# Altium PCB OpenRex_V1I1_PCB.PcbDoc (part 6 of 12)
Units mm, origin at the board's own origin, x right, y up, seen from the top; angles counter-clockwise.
Board outline 70 x 95 mm, 10 copper layers (L1, L2, L3, L4 (PWR), L5 (PWR), L6 (PWR), L7 (PWR), L8, L9, L10), stack 1.632 mm thick; 1080 components, 708 nets, 3831 pads, 2373 vias.
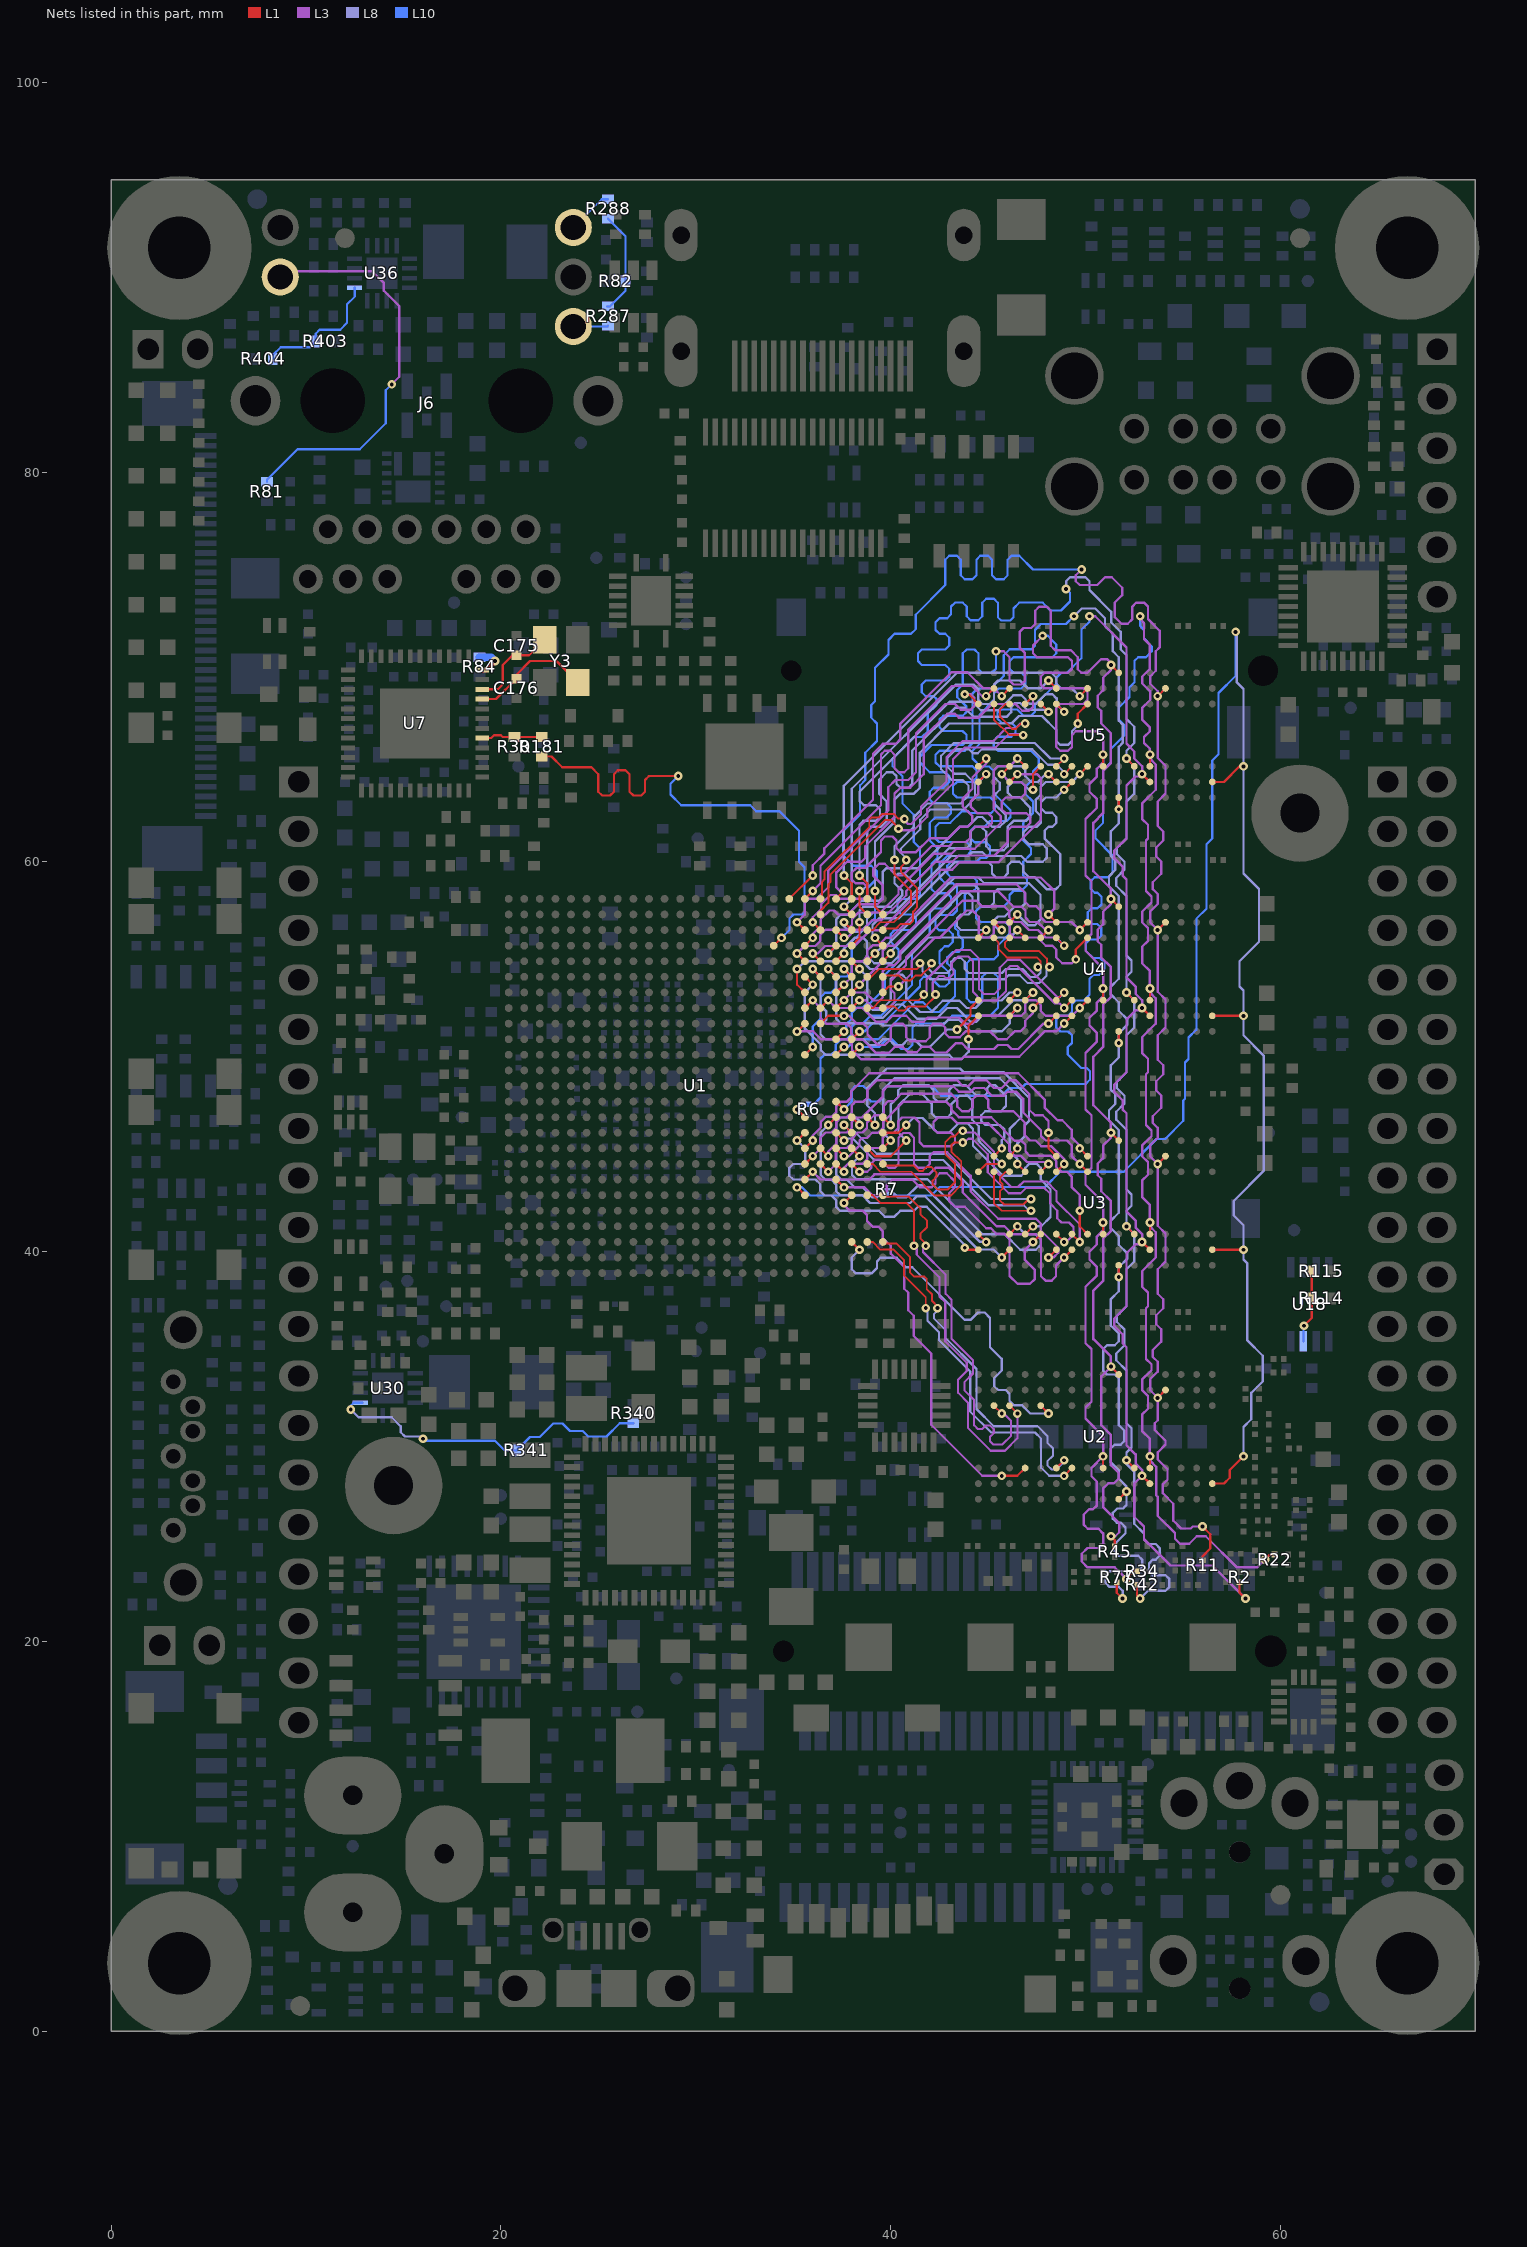
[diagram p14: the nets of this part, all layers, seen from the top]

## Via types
v1: diameter 0.45, hole 0.2, L1 to L10, tented both sides, 2369 vias
v2: diameter 1, hole 0.5, L1 to L10, tented top, 4 vias

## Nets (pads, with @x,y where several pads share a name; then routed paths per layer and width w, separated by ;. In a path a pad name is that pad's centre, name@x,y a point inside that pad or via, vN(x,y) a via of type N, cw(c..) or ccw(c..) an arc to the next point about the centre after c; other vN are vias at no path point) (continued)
DRAM_D16: U1.AB7 U3.E3 | length 19.1
  L1 w0.114: U1.AB7@37.2,43.7 v1(37.6,43.3) ; v1(47.3,40.5) U3.E3@47.7,40.9
  L3 w0.12: v1(37.6,43.3) 38.656,43.3 39.056,42.9 39.6,42.9 39.793,43.093 39.793,43.393 40.085,43.685 41.115,43.685 41.5,43.3 42.1,43.3 42.3,43.5 42.3,43.8 42.52,44.02 42.88,44.02 43.3,43.6 43.3,43.3 43,43 43,42.6 43.3,42.3 43.8,42.3 44.9,41.2 45.14,41.2 45.418,40.922 45.822,40.922 46.1,40.644 46.1,38.756 46.506,38.35 47.15,38.35 47.4,38.6 47.4,39.055 46.885,39.571 46.885,40.085 v1(47.3,40.5)
DRAM_D17: U1.AA8 U3.F7 | length 19.1
  L1 w0.114: U1.AA8@36.4,44.5 v1(36.8,44.1) ; U3.F7@48.5,44.1 v1(48.9,44.5)
  L3 w0.12: v1(36.8,44.1) 37.185,44.485 37.185,45.085 37.415,45.315 37.759,45.315 38.009,45.565 38.009,45.809 38.315,46.115 38.559,46.115 38.785,46.341 38.785,46.629 39.156,47 39.5,47 39.656,47.156 39.656,47.5 39.871,47.715 40.159,47.715 40.544,48.1 43.1,48.1 43.415,47.785 43.415,47.441 43.656,47.2 44,47.2 44.215,47.415 44.215,47.815 44.385,47.985 44.815,47.985 45,47.8 45,47.4 45.2,47.2 46.3,47.2 46.885,46.615 46.885,45.971 47.155,45.7 47.444,45.7 47.685,45.459 47.744,45.4 48.255,45.4 48.9,44.755 v1(48.9,44.5)
DRAM_D18: U1.AB9 U3.H3 | length 19.1
  L1 w0.114: U1.AB9@37.2,45.3 v1(37.6,44.9) ; v1(49.7,42.1) 49.7,41.3 U3.H3@50.1,40.9
  L3 w0.12: v1(37.6,44.9) 37.856,44.9 38.4,45.444 38.4,45.7 38.535,45.835 38.791,45.835 39.056,46.1 39.344,46.1 39.615,46.371 39.615,46.659 40.656,47.7 42.844,47.7 43.1,47.444 43.1,47.3 43.5,46.9 45.155,46.9 46.371,45.685 46.715,45.685 46.915,45.485 46.915,45.141 47.141,44.915 48.229,44.915 48.5,44.644 48.5,44.356 48.771,44.085 49.059,44.085 49.285,43.859 49.285,43.315 49.7,42.9 v1(49.7,42.1)
DRAM_D19: U1.Y9 U3.H8 | length 19.1
  L1 w0.114: U1.Y9@35.6,45.3 v1(36,45.7) ; v1(49.7,45.3) U3.H8@50.1,44.9
  L3 w0.12: v1(36,45.7) 36,45.956 36.415,46.371 36.415,46.659 36.671,46.915 36.959,46.915 37.215,47.171 37.215,47.459 37.441,47.685 37.729,47.685 37.985,47.941 37.985,48.229 38.906,49.15 46.55,49.15 47.9,47.8 47.9,47.4 48.556,46.744 48.8,46.744 49.285,46.259 49.285,45.855 49.7,45.44 v1(49.7,45.3)
DRAM_D20: U1.Y7 U3.G2 | length 19.1
  L1 w0.114: U1.Y7@35.6,43.7 v1(36,44.1) ; v1(48.9,39.7) U3.G2@49.3,40.1
  L3 w0.12: v1(36,44.1) 36.4,43.7 38.9,43.7 39.165,43.965 41.965,43.965 42.3,44.3 43,44.3 43.7,43.6 43.7,43.036 45.436,41.3 45.84,41.3 46.255,40.885 47.459,40.885 47.715,40.629 47.715,38.741 47.941,38.515 48.259,38.515 48.485,38.741 48.485,39.285 v1(48.9,39.7)
DRAM_D21: U1.Y8 U3.F8 | length 19.1
  L1 w0.114: U1.Y8@35.6,44.5 v1(36,44.9) ; v1(48.1,46.1) 48.1,45.3 U3.F8@48.5,44.9
  L3 w0.12: v1(36,44.9) 36.385,45.285 36.385,45.829 36.671,46.115 36.959,46.115 37.215,46.371 37.215,46.659 37.441,46.885 37.729,46.885 38,47.156 38,47.5 38.2,47.7 38.6,47.7 38.8,47.9 38.8,48.285 39.315,48.8 43.4,48.8 43.7,48.5 44,48.5 44.3,48.8 44.9,48.8 45.3,48.4 45.7,48.4 46.1,48.8 46.4,48.8 47.115,48.085 47.115,47.285 47.4,47 47.8,47 48.1,46.7 v1(48.1,46.1)
DRAM_D22: U1.AC8 U3.F2 | length 19.1
  L1 w0.114: U1.AC8@38,44.5 v1(38.4,44.1) ; v1(48.1,39.7) U3.F2@48.5,40.1
  L3 w0.12: v1(38.4,44.1) 38.8,44.1 39,44.3 39,44.525 39.2,44.725 39.475,44.725 39.9,44.3 40.205,44.3 40.4,44.495 40.4,45.844 40.641,46.085 40.959,46.085 41.2,45.844 41.2,44.5 41.4,44.3 41.8,44.3 42,44.5 42,44.9 42.2,45.1 42.9,45.1 44.1,43.9 44.1,43.1 45.515,41.685 47.459,41.685 47.7,41.444 47.7,41.1 48.6,40.2 48.6,39.944 48.356,39.7 v1(48.1,39.7)
DRAM_D23: U1.AA9 U3.H7 | length 19.1
  L1 w0.114: U1.AA9@36.4,45.3 v1(36.8,44.9) ; v1(49.7,44.5) U3.H7@50.1,44.1
  L3 w0.12: v1(36.8,44.9) 36.8,45.14 37.2,45.54 37.2,45.9 37.415,46.115 37.759,46.115 38,46.356 38,46.644 38.241,46.885 38.529,46.885 39.6,47.956 39.6,48.244 39.841,48.485 43.215,48.485 43.5,48.2 44.1,48.2 44.3,48.4 44.8,48.4 45.2,48 45.8,48 46,48.2 46.449,48.2 46.8,47.849 46.8,47.144 47.715,46.229 47.715,45.941 47.956,45.7 49.044,45.7 49.285,45.459 49.285,44.915 v1(49.7,44.5)
DRAM_D24: U1.AE9 U3.D7 | length 15.4
  L1 w0.114: U1.AE9@39.6,45.3 v1(40,45.7) ; v1(46.5,44.5) U3.D7@46.9,44.1
  L8 w0.12: v1(40,45.7) 39.615,46.085 39.615,48.315 40.2,48.9 45.6,48.9 46.7,47.8 46.7,46.9 46.115,46.315 46.115,45.141 46.5,44.756 v1(46.5,44.5)
DRAM_D25: U1.Y10 U3.A2 | length 15.4
  L1 w0.114: v1(35.2,45.7) U1.Y10@35.6,46.1 ; v1(43.8,40.2) 43.9,40.1 U3.A2@44.5,40.1
  L8 w0.12: v1(35.2,45.7) 35.615,45.285 35.615,44.6 35.515,44.5 35,44.5 34.8,44.3 34.8,43.9 35,43.7 36.144,43.7 36.385,43.459 36.385,43.115 36.615,42.885 36.959,42.885 37.215,42.629 37.215,42.285 37.4,42.1 39.4,42.1 39.7,41.8 40.2,41.8 40.5,42.1 41.2,42.1 41.4,42.3 41.844,42.3 43.8,40.344 v1(43.8,40.2)
DRAM_D26: U1.AE11 U3.B8 | length 15.4
  L1 w0.114: U1.AE11@39.6,46.9 v1(40,46.5) ; U3.B8@45.3,44.9 v1(45.7,45.3)
  L8 w0.12: v1(40,46.5) 40,47.556 40.385,47.941 40.385,48.285 40.645,48.545 41.955,48.545 42.2,48.3 42.2,47.9 42.4,47.7 42.8,47.7 43,47.9 43,48.3 43.245,48.545 43.855,48.545 44.4,48 44.8,48 44.955,48.155 44.955,48.4 45.1,48.545 45.355,48.545 45.915,47.985 45.915,47.471 45.644,47.2 44.85,47.2 44.65,47 44.65,46.7 44.85,46.5 45.6,46.5 45.835,46.265 45.835,45.854 45.7,45.719 v1(45.7,45.3)
DRAM_D27: U1.AB11 U3.C2 | length 15.4
  L1 w0.114: v1(36.8,46.5) U1.AB11@37.2,46.9 ; v1(45.7,39.7) U3.C2@46.1,40.1
  L8 w0.12: v1(36.8,46.5) 36.415,46.115 36.415,43.941 36.671,43.685 36.959,43.685 37.2,43.444 37.2,43.1 37.4,42.9 38.544,42.9 38.944,42.5 41,42.5 41.35,42.85 41.75,42.85 44.485,40.115 45.285,40.115 v1(45.7,39.7)
DRAM_D28: U1.AC9 U3.C3 | length 15.4
  L1 w0.114: U1.AC9@38,45.3 v1(38.4,44.9) ; U3.C3@46.1,40.9 v1(46.5,41.3)
  L8 w0.12: v1(38.4,44.9) 38.015,44.515 38.015,43.941 38.241,43.715 41.885,43.715 44.7,40.9 45.844,40.9 46.644,40.1 47.444,40.1 47.685,40.341 47.685,40.659 47.459,40.885 46.915,40.885 v1(46.5,41.3)
DRAM_D29: U1.AD9 U3.A7 | length 15.4
  L1 w0.114: U1.AD9@38.8,45.3 39.2,44.9 40,44.9 v1(40.8,45.7) ; U3.A7@44.5,44.1 44.9,44.5 v1(45.7,44.5)
  L8 w0.12: v1(40.8,45.7) 40.4,46.1 40.4,47.5 41,48.1 41.6,48.1 42.1,47.6 42.1,47.1 42.3,46.9 42.928,46.9 43.1,47.072 43.1,47.553 43.547,48 43.944,48 44.185,47.759 44.185,46.769 44.515,46.439 44.515,45.685 v1(45.7,44.5)
DRAM_D30: U1.AD11 U3.C8 | length 15.4
  L1 w0.114: U1.AD11@38.8,46.9 v1(39.2,46.5) ; U3.C8@46.1,44.9 v1(46.5,45.3)
  L8 w0.12: v1(39.2,46.5) 39.2,47.1 38.8,47.5 38.8,48.4 39.8,49.4 43.556,49.4 43.741,49.215 45.785,49.215 47.1,47.9 47.1,46.7 46.885,46.485 46.885,45.941 46.5,45.556 v1(46.5,45.3)
DRAM_D31: U1.AC11 U3.A3 | length 15.4
  L1 w0.114: U1.AC11@38,46.9 v1(38.4,46.5) ; U3.A3@44.5,40.9 v1(44.9,40.5)
  L8 w0.12: v1(38.4,46.5) 38.4,46.7 38.215,46.885 37.385,46.885 37.2,46.7 37.2,43.956 37.471,43.685 37.759,43.685 38.144,43.3 38.54,43.3 39.04,42.8 39.3,42.8 39.7,43.2 39.956,43.2 40.356,42.8 40.8,42.8 41.4,43.4 41.69,43.4 44.59,40.5 v1(44.9,40.5)
DRAM_D32: U1.AA17 U4.E3 | length 16.3
  L1 w0.114: U1.AA17@36.4,51.7 36.8,52.1 v1(37.6,52.1) ; v1(47.3,52.5) U4.E3@47.7,52.9
  L3 w0.12: v1(37.6,52.1) 37.856,52.1 38.241,51.715 38.585,51.715 38.815,51.485 38.815,51.141 39.356,50.6 39.7,50.6 40,50.9 40,51.5 40.2,51.7 40.6,51.7 40.8,51.5 40.8,51 41,50.8 41.8,50.8 42,51 42,51.5 42.2,51.7 42.6,51.7 42.8,51.5 42.8,51.2 43,51 43.544,51 43.844,51.3 45.1,51.3 45.5,50.9 45.956,50.9 46.356,51.3 46.644,51.3 46.9,51.556 46.9,51.844 47.3,52.244 v1(47.3,52.5)
DRAM_D33: U1.AA18 U4.H3 | length 16.4
  L1 w0.114: U1.AA18@36.4,52.5 v1(36.8,52.9) ; v1(49.7,52.5) U4.H3@50.1,52.9
  L3 w0.12: v1(36.8,52.9) 37.2,52.5 38.544,52.5 39.244,51.8 39.8,51.8 40.1,52.1 40.8,52.1 41.1,51.8 41.7,51.8 41.915,52.015 43.5,52.015 43.815,51.7 44.2,51.7 44.6,52.1 46.7,52.1 46.9,52.3 46.9,52.7 47.1,52.9 47.444,52.9 47.7,52.644 47.7,52.35 47.95,52.1 49.3,52.1 v1(49.7,52.5)
DRAM_D34: U1.AC18 U4.F7 | length 16.4
  L1 w0.114: U1.AC18@38,52.5 v1(38.4,52.9) ; U4.F7@48.5,56.1 v1(48.9,55.7)
  L3 w0.12: v1(38.4,52.9) 38.7,52.9 39.1,52.5 39.9,52.5 40.2,52.8 40.2,53.256 40.015,53.441 40.015,53.915 40.79,54.69 40.79,55.1 43.69,58 44.4,58 44.685,57.715 45.829,57.715 46.085,57.459 46.085,57.171 46.341,56.915 46.685,56.915 47.1,56.5 47.555,56.5 47.941,56.115 48.485,56.115 v1(48.9,55.7)
DRAM_D35: U1.AE19 U4.H7 | length 16.3
  L1 w0.114: U1.AE19@39.6,53.3 39.9,53.6 v1(40.4,53.6) ; v1(49.5,55) 49.5,55.5 U4.H7@50.1,56.1
  L3 w0.12: v1(40.4,53.6) 41.08,54.28 41.08,54.924 42.256,56.1 42.5,56.1 43.9,57.5 44.2,57.5 44.515,57.185 44.515,56.341 44.741,56.115 45.059,56.115 45.285,56.341 45.285,56.685 45.5,56.9 45.9,56.9 46.115,56.685 46.115,56.341 46.341,56.115 47.545,56.115 47.96,55.7 48.3,55.7 48.5,55.5 48.5,55.1 48.8,54.8 49.3,54.8 v1(49.5,55)
DRAM_D36: U1.Y17 U4.G2 | length 16.3
  L1 w0.114: v1(35.2,51.3) U1.Y17@35.6,51.7 ; v1(48.9,51.7) U4.G2@49.3,52.1
  L3 w0.12: v1(35.2,51.3) 36.03,51.3 36.43,50.9 37.744,50.9 38.015,50.629 38.015,50.341 38.481,49.875 43.631,49.875 43.756,50 46.6,50 47.9,51.3 48.5,51.3 v1(48.9,51.7)
DRAM_D37: U1.Y18 U4.F2 | length 16.3
  L1 w0.114: U1.Y18@35.6,52.5 v1(36,52.9) ; v1(48.1,51.7) U4.F2@48.5,52.1
  L3 w0.12: v1(36,52.9) 36.4,52.5 36.4,52 36.715,51.685 37.759,51.685 37.985,51.459 37.985,51.171 38.256,50.9 38.544,50.9 39.244,50.2 39.9,50.2 40.215,50.515 40.613,50.515 40.893,50.235 41.335,50.235 41.615,50.515 41.985,50.515 42.285,50.215 42.871,50.215 43.356,50.7 43.644,50.7 43.944,50.4 45.3,50.4 45.5,50.6 46,50.6 46.2,50.4 46.544,50.4 47.844,51.7 v1(48.1,51.7)
DRAM_D38: U1.AB19 U4.F8 | length 16.3
  L1 w0.114: U1.AB19@37.2,53.3 v1(37.6,53.7) ; v1(48.1,57.3) U4.F8@48.5,56.9
  L3 w0.12: v1(37.6,53.7) 38,54.1 38,54.7 38.2,54.9 38.544,54.9 38.815,55.171 38.815,55.459 39.071,55.715 39.359,55.715 39.744,56.1 40,56.1 43.1,59.2 47.7,59.2 48.4,58.5 48.4,57.6 v1(48.1,57.3)
DRAM_D39: U1.AC19 U4.H8 | length 16.3
  L1 w0.114: U1.AC19@38,53.3 v1(38.4,53.7) ; v1(49.7,56.5) U4.H8@50.1,56.9
  L3 w0.12: v1(38.4,53.7) 39.585,54.885 39.585,55.429 39.856,55.7 40.2,55.7 43.35,58.85 46.45,58.85 46.9,58.4 46.9,57.955 47.141,57.715 47.47,57.715 47.685,57.5 47.685,57.171 47.941,56.915 49.285,56.915 v1(49.7,56.5)
DRAM_D40: U1.Y19 U4.D7 | length 14.4
  L1 w0.114: v1(35.2,54.5) 35.2,53.7 U1.Y19@35.6,53.3 ; v1(46.5,56.5) U4.D7@46.9,56.1
  L8 w0.12: v1(35.2,54.5) 35.6,54.9 38.544,54.9 38.944,54.5 40.3,54.5 41.915,56.115 46.115,56.115 v1(46.5,56.5)
DRAM_D41: U1.AB20 U4.C2 | length 14.4
  L1 w0.114: v1(36.8,54.5) U1.AB20@37.2,54.1 ; U4.C2@46.1,52.1 v1(46.5,52.5)
  L8 w0.12: v1(36.8,54.5) 37.215,54.085 37.215,51.941 37.441,51.715 39.485,51.715 39.6,51.6 42.64,51.6 42.94,51.9 43.5,51.9 44.1,51.3 45.7,51.3 46.115,51.715 46.115,52.115 v1(46.5,52.5)
DRAM_D42: U1.AB21 U4.A7 | length 14.4
  L1 w0.114: U1.AB21@37.2,54.9 v1(37.6,55.3) ; U4.A7@44.5,56.1 v1(44.9,56.5)
  L8 w0.12: v1(37.6,55.3) 37.6,55.556 38.144,56.1 38.6,56.1 38.785,55.915 38.785,55.178 ; 38.781,55.174 39.156,54.8 40.044,54.8 43.644,58.4 44,58.4 44.2,58.2 44.2,57.5 44,57.3 43.6,57.3 43.4,57.1 43.4,56.7 43.6,56.5 v1(44.9,56.5)
DRAM_D43: U1.AD21 U4.C8 | length 14.4
  L1 w0.114: U1.AD21@38.8,54.9 v1(39.2,55.3) ; U4.C8@46.1,56.9 v1(46.5,57.3)
  L8 w0.12: v1(39.2,55.3) 39.6,55.7 39.785,55.7 43.285,59.2 44.5,59.2 44.8,58.9 47.1,58.9 47.685,58.315 47.685,57.035 47.4,56.75 47.05,56.75 v1(46.5,57.3)
DRAM_D44: U1.Y20 U4.A2 | length 14.4
  L1 w0.114: U1.Y20@35.6,54.1 v1(36,53.7) ; v1(44,50.9) 44,51.6 U4.A2@44.5,52.1
  L8 w0.12: v1(36,53.7) 35.6,53.3 35.6,51.444 36.415,50.629 36.415,50.341 36.656,50.1 43,50.1 43.2,49.9 43.644,49.9 44,50.256 v1(44,50.9)
DRAM_D45: U1.AA20 U4.A3 | length 14.4
  L1 w0.114: v1(36,54.5) U1.AA20@36.4,54.1 ; v1(43.4,51.4) 44.1,52.1 44.1,52.5 U4.A3@44.5,52.9
  L8 w0.12: v1(36,54.5) 36.4,54.1 36.4,52.628 36.7,52.328 36.7,51.9 36.4,51.6 36.4,51.156 36.656,50.9 38.6,50.9 38.9,50.6 39.3,50.6 39.6,50.9 39.9,50.9 40.2,50.6 40.6,50.6 40.878,50.878 41.222,50.878 41.6,50.5 42,50.5 42.9,51.4 v1(43.4,51.4)
DRAM_D46: U1.AE21 U4.B8 | length 14.4
  L1 w0.114: U1.AE21@39.6,54.9 v1(40,55.3) ; U4.B8@45.3,56.9 v1(45.7,56.5)
  L8 w0.12: v1(40,55.3) 40,55.4 43.4,58.8 44.3,58.8 44.5,58.6 44.5,57.9 44.7,57.7 45.1,57.7 45.3,57.9 45.3,58.4 45.5,58.6 46.7,58.6 46.885,58.415 46.885,57.86 46.71,57.685 46.341,57.685 45.856,57.2 45.5,57.2 45.3,57 45.3,56.744 45.544,56.5 v1(45.7,56.5)
DRAM_D47: U1.AC21 U4.C3 | length 14.4
  L1 w0.114: U1.AC21@38,54.9 v1(38.4,54.5) ; U4.C3@46.1,52.9 v1(46.5,53.3)
  L8 w0.12: v1(38.4,54.5) 38.8,54.1 38.8,52.7 39.1,52.4 39.5,52.4 40,52.9 40,54 40.2,54.2 40.6,54.2 40.8,54 40.8,53 41.5,52.3 42.1,52.3 42.675,52.875 43.525,52.875 43.9,52.5 44.356,52.5 44.741,52.885 45.685,52.885 46.1,53.3 v1(46.5,53.3)
DRAM_D48: U1.AC22 U5.E3 | length 21.7
  L1 w0.114: U1.AC22@38,55.7 38.4,56.1 v1(38.4,56.9) ; v1(47.3,63.7) 47.3,64.5 U5.E3@47.7,64.9
  L8 w0.12: v1(38.4,56.9) 38.4,57.5 38.6,57.7 40,57.7 40.6,58.3 40.6,58.5 40.2,58.9 40.2,59.2 40.4,59.4 40.7,59.4 41.1,59 41.3,59 43,60.7 43.9,60.7 44.1,60.9 44.1,61.544 44.341,61.785 44.659,61.785 44.9,61.544 44.9,60.8 45.1,60.6 45.8,60.6 46,60.8 46,61.8 46.3,62.1 46.955,62.1 47.155,62.3 47.155,62.789 46.629,63.315 46.24,63.315 46.015,63.541 46.015,63.859 46.24,64.085 46.715,64.085 47.1,63.7 v1(47.3,63.7)
DRAM_D49: U1.AE22 U5.G2 | length 21.7
  L1 w0.114: v1(39.2,56.1) U1.AE22@39.6,55.7 ; v1(48.9,63.7) U5.G2@49.3,64.1
  L8 w0.12: v1(39.2,56.1) 39.065,56.235 39.065,56.765 39.4,57.1 40.41,57.1 43.295,59.985 45.015,59.985 45.2,59.8 45.2,59.4 45.4,59.2 45.8,59.2 46,59.4 46,59.8 46.2,60 46.6,60 46.8,59.8 46.8,59.5 47.085,59.215 47.385,59.215 48,58.6 48.475,58.6 48.7,58.825 48.7,60.4 47.9,61.2 47.9,61.6 48.1,61.8 48.3,61.8 48.5,62 48.5,62.3 48.285,62.515 47.941,62.515 47.715,62.741 47.715,63.059 47.956,63.3 48.5,63.3 v1(48.9,63.7)
DRAM_D50: U1.AE24 U5.H7 | length 21.7
  L1 w0.114: v1(39.2,58.5) 39.2,57.7 U1.AE24@39.6,57.3 ; v1(49.6,67.1) 49.6,67.6 U5.H7@50.1,68.1
  L8 w0.12: v1(39.2,58.5) 39.2,61.044 40.2,62.044 40.2,63.2 40.5,63.5 41.2,63.5 41.5,63.8 41.5,65.6 43,67.1 46.2,67.1 46.585,67.485 47.771,67.485 48.5,66.756 48.5,66.2 48.7,66 49.1,66 49.3,66.2 49.3,66.7 49.6,67 v1(49.6,67.1)
DRAM_D51: U1.AC24 U5.F8 | length 21.7
  L1 w0.114: v1(37.6,57.7) U1.AC24@38,57.3 ; v1(48.1,69.3) U5.F8@48.5,68.9
  L8 w0.12: v1(37.6,57.7) 38,58.1 38,63.75 43.35,69.1 44.25,69.1 44.5,68.85 44.5,68.3 44.7,68.1 45.1,68.1 45.3,68.3 45.3,69.1 45.507,69.307 46.633,69.307 47.025,68.915 47.715,68.915 v1(48.1,69.3)
DRAM_D52: U1.AB22 U5.F2 | length 21.7
  L1 w0.114: v1(36.8,55.3) U1.AB22@37.2,55.7 ; v1(48.1,64.5) U5.F2@48.5,64.1
  L8 w0.12: v1(36.8,55.3) 36.83,55.3 37.2,55.67 37.2,57.044 37.441,57.285 37.785,57.285 38.5,58 39.4,58 39.585,58.185 39.585,59.485 39.78,59.68 41.424,59.68 43.559,61.815 43.975,61.815 44.46,62.3 44.7,62.3 45.2,61.8 45.6,61.8 45.9,62.1 45.9,62.4 45.3,63 45.3,63.4 45.6,63.7 45.6,64.056 45.3,64.356 45.3,64.7 45.5,64.9 46.7,64.9 46.9,64.7 46.9,64.4 47.2,64.1 47.56,64.1 47.96,64.5 v1(48.1,64.5)
DRAM_D53: U1.AC23 U5.H3 | length 21.7
  L1 w0.114: v1(37.6,56.9) U1.AC23@38,56.5 ; v1(49.7,64.5) U5.H3@50.1,64.9
  L8 w0.12: v1(37.6,56.9) 37.6,56.7 37.9,56.4 38.444,56.4 38.785,56.741 38.785,57.085 39.1,57.4 40.2,57.4 43.1,60.3 44,60.3 44.2,60.5 44.7,60.5 44.9,60.3 46.696,60.3 46.996,60 47.8,60 48,60.2 48,60.7 47.8,60.9 47.1,60.9 46.8,61.2 46.8,61.5 47.1,61.8 47.5,61.8 47.7,62 47.7,62.36 47.435,62.625 47.435,63.175 47.7,63.44 47.7,63.844 47.956,64.1 49.3,64.1 v1(49.7,64.5)
DRAM_D54: U1.AD25 U5.F7 | length 21.7
  L1 w0.114: v1(38.4,59.3) 38.8,58.9 U1.AD25@38.8,58.1 ; U5.F7@48.5,68.1 v1(48.9,67.7)
  L8 w0.12: v1(38.4,59.3) 38.4,61.9 38.6,62.1 39.25,62.1 39.45,62.3 39.45,62.7 39.25,62.9 38.625,62.9 38.4,63.125 38.4,63.596 43.019,68.215 44.185,68.215 44.623,67.777 45.521,67.777 46.294,68.55 46.705,68.55 47.141,68.115 47.459,68.115 47.944,68.6 48.3,68.6 48.515,68.385 48.515,68.085 v1(48.9,67.7)
DRAM_D55: U1.AC25 U5.H8 | length 21.7
  L1 w0.114: v1(37.6,59.3) 38,58.9 U1.AC25@38,58.1 ; v1(49.7,68.5) U5.H8@50.1,68.9
  L8 w0.12: v1@37.6,59.3 37.6,63.9 43.4,69.7 48.244,69.7 48.5,69.444 48.5,69.156 48.756,68.9 49.3,68.9 v1(49.7,68.5)
DRAM_D56: U1.AB25 U5.D7 | length 19.1
  L1 w0.114: U1.AB25@37.2,58.1 v1(37.6,58.5) ; U5.D7@46.9,68.1 v1(47.3,68.5)
  L3 w0.12: v1(37.6,58.5) 37.4,58.5 37.215,58.685 37.215,59.459 37.756,60 38.5,60 38.7,60.2 38.7,60.8 40.2,62.3 40.2,63.5 40.5,63.8 41,63.8 41.7,64.5 41.7,66.4 42.9,67.6 43.3,67.6 43.5,67.4 44.5,67.4 45.2,68.1 46.4,68.1 46.75,67.75 47.1,67.75 47.3,67.95 v1(47.3,68.5)
DRAM_D57: U1.AA21 U5.C2 | length 19.1
  L1 w0.114: v1(36,55.3) U1.AA21@36.4,54.9 ; U5.C2@46.1,64.1 v1(46.5,64.5)
  L3 w0.12: v1(36,55.3) 36.256,55.3 36.641,55.685 38.14,55.685 38.94,56.485 39.485,56.485 42.6,59.6 43.156,59.6 43.541,59.985 45.541,59.985 47.715,62.159 47.715,64.285 47.5,64.5 v1(46.5,64.5)
DRAM_D58: U1.Y25 U5.B8 | length 19.1
  L1 w0.114: U1.Y25@35.6,58.1 v1(36,58.5) ; v1(44.9,68.5) U5.B8@45.3,68.9
  L3 w0.12: v1(36,58.5) 36.4,58.9 36.4,59.8 39.5,62.9 39.5,65.5 39.7,65.7 40,65.7 40.2,65.5 40.2,64.8 40.4,64.6 40.7,64.6 40.9,64.8 40.9,66.79 43.135,69.025 44.171,69.025 44.696,68.5 v1(44.9,68.5)
DRAM_D59: U1.Y22 U5.A2 | length 19.1
  L1 w0.114: U1.Y22@35.6,55.7 v1(36,56.1) ; U5.A2@44.5,64.1 v1(44.9,64.5)
  L3 w0.12: v1(36,56.1) 36,56.3 36.415,56.715 36.415,57.059 36.856,57.5 37.1,57.5 37.3,57.3 37.8,57.3 38.325,57.825 39.325,57.825 39.585,58.085 39.585,58.815 39.1,59.3 39.1,59.6 39.4,59.9 39.7,59.9 40.3,59.3 40.6,59.3 42.111,60.811 43.011,60.811 43.215,61.015 43.859,61.015 44.085,61.241 44.085,61.545 44.34,61.8 45,61.8 45.2,62 45.2,62.3 45,62.5 44.44,62.5 44.1,62.84 44.1,63.1 44.5,63.5 44.5,64.1 v1(44.9,64.5)
DRAM_D60: U1.AB23 U5.C3 | length 19.1
  L1 w0.114: U1.AB23@37.2,56.5 v1(37.6,56.1) ; v1(45.7,64.5) U5.C3@46.1,64.9
  L3 w0.12: v1(37.6,56.1) 37.755,56.1 38.17,56.515 38.559,56.515 39.044,57 39.51,57 40.8,58.29 40.8,58.5 42.302,60.002 ; 42.302,60.004 43.162,60.004 ; 43.162,60.002 43.488,60.328 45.328,60.328 46,61 46,61.6 46.2,61.8 46.96,61.8 47.16,62 47.16,62.3 46.96,62.5 45.9,62.5 45.7,62.7 45.7,63.1 45.9,63.3 46.7,63.3 46.9,63.5 46.9,63.9 46.7,64.1 46.1,64.1 v1(45.7,64.5)
DRAM_D61: U1.AA23 U5.A3 | length 19.1
  L1 w0.114: v1(36,56.9) U1.AA23@36.4,56.5 ; U5.A3@44.5,64.9 v1(44.9,65.3)
  L3 w0.12: v1(36,56.9) 36,57.156 36.434,57.589 36.434,57.834 36.9,58.3 37.2,58.3 37.385,58.115 38.615,58.115 38.8,58.3 38.8,58.7 38.6,58.9 38.2,58.9 38,59.1 38,59.444 38.241,59.685 38.685,59.685 39.5,60.5 39.5,61.1 39.7,61.3 40.1,61.3 40.3,61.1 40.3,60.7 40.5,60.5 41.3,60.5 42.015,61.215 42.971,61.215 43.556,61.8 43.944,61.8 44.185,62.041 44.185,62.359 43.7,62.844 43.7,63.256 44.2,63.756 44.2,64.344 44.9,65.044 v1(44.9,65.3)
DRAM_D62: U1.Y23 U5.A7 | length 19.1
  L1 w0.114: v1(35.2,56.9) U1.Y23@35.6,56.5 ; v1(43.8,68.6) 44,68.6 U5.A7@44.5,68.1
  L3 w0.12: v1(35.2,56.9) 35.585,57.285 35.585,57.885 35.8,58.1 36.2,58.1 36.8,58.7 36.8,59.556 39.88,62.636 39.88,63.83 40.25,64.2 40.9,64.2 41.3,64.6 41.3,66.6 42.8,68.1 43.3,68.1 43.6,67.8 44.1,67.8 44.3,68 44.3,68.4 44.1,68.6 v1(43.8,68.6)
DRAM_D63: U1.W25 U5.C8 | length 19.1
  L1 w0.114: U1.W25@34.8,58.1 v1(36,59.3) ; v1(45.7,68.5) U5.C8@46.1,68.9
  L3 w0.12: v1(36,59.3) 36,59.83 36.6,60.43 36.6,60.7 39.09,63.19 39.09,65.546 39.6,66.056 40.256,66.056 40.5,66.3 40.5,67.1 43.125,69.725 43.93,69.725 44.755,68.9 45.3,68.9 v1(45.7,68.5)
DRAM_DQM0: U1.AC3 U2.E7 | length 19.1
  L1 w0.114: U1.AC3@38,40.5 v1(38.4,40.1) ; U2.E7@47.7,32.1 v1(48.1,31.7)
  L8 w0.12: v1(38.4,40.1) 38,39.7 38,39.1 38.2,38.9 39.035,38.9 39.3,39.165 39.3,39.5 39.485,39.685 40.311,39.685 40.8,39.196 41.104,39.196 43.8,36.5 44.1,36.5 44.475,36.875 44.825,36.875 45.1,36.6 45.1,35.1 45.7,34.5 45.7,33.9 45.315,33.515 45.315,33.1 45.515,32.9 45.9,32.9 46.1,32.7 46.1,32.356 46.341,32.115 46.745,32.115 47.16,31.7 v1(48.1,31.7)
DRAM_DQM1: U1.AC6 U2.D3 | length 20.4
  L1 w0.114: v1(37.6,42.5) U1.AC6@38,42.9 ; v1(45.7,28.5) 46.5,28.5 U2.D3@46.9,28.9
  L3 w0.12: v1(37.6,42.5) 37.6,42.4 37.885,42.115 38.554,42.115 38.785,41.884 38.785,41.571 39.071,41.285 39.359,41.285 39.585,41.059 39.585,40.715 40,40.3 40,39.9 40.7,39.2 40.7,38.1 40.9,37.9 40.9,36.996 41.18,36.716 41.18,35.68 42.085,34.775 42.085,31.115 44.7,28.5 v1(45.7,28.5)
DRAM_DQM2: U1.AB8 U3.E7 | length 19.1
  L1 w0.114: U1.AB8@37.2,44.5 v1(37.6,44.1) ; U3.E7@47.7,44.1 v1(48.1,44.5)
  L3 w0.12: v1(37.6,44.1) 37.6,44.3 37.815,44.515 38.559,44.515 38.8,44.756 38.8,45.1 39.015,45.315 39.417,45.315 39.6,45.498 39.6,45.844 39.841,46.085 40.129,46.085 40.385,46.341 40.385,46.685 40.585,46.885 41.215,46.885 41.48,46.62 41.48,45.62 41.7,45.4 43.1,45.4 43.3,45.6 43.3,45.9 43.1,46.1 42.4,46.1 42.2,46.3 42.2,46.65 42.435,46.885 43.115,46.885 43.4,46.6 45,46.6 46.085,45.515 46.085,45.171 46.341,44.915 46.685,44.915 47,44.6 48,44.6 v1(48.1,44.5)
DRAM_DQM3: U1.AE10 U3.D3 | length 15.4
  L1 w0.114: U1.AE10@39.6,46.1 40.4,46.1 v1(40.8,46.5) ; U3.D3@46.9,40.9 v1(47.3,41.3)
  L8 w0.12: v1(40.8,46.5) 41.16,46.86 41.64,46.86 42.4,46.1 43,46.1 43.485,46.585 43.935,46.585 44.22,46.3 44.22,45.436 45.756,43.9 46.7,43.9 46.9,44.1 46.9,44.3 47.1,44.5 47.5,44.5 47.7,44.3 47.7,43.7 48.2,43.2 48.2,41.775 47.725,41.3 v1(47.3,41.3)
DRAM_DQM4: U1.AB18 U4.E7 | length 16.4
  L1 w0.114: U1.AB18@37.2,52.5 v1(37.6,52.9) ; U4.E7@47.7,56.1 v1(48.1,56.5)
  L3 w0.12: v1(37.6,52.9) 38,53.3 38.7,53.3 39.115,52.885 39.435,52.885 39.6,53.05 39.6,54.4 39.9,54.7 40.2,54.7 40.5,55 40.5,55.4 43.6,58.5 45.5,58.5 46.3,57.7 46.715,57.7 46.915,57.5 46.915,57.141 47.141,56.915 47.536,56.915 47.951,56.5 v1(48.1,56.5)
DRAM_DQM5: U1.AC20 U4.D3 | length 14.4
  L1 w0.114: v1(37.6,54.5) U1.AC20@38,54.1 ; U4.D3@46.9,52.9 v1(47.3,53.3)
  L8 w0.12: v1(37.6,54.5) 38.015,54.085 38.015,52.685 38.2,52.5 38.6,52.5 39.1,52 39.6,52 40.285,52.685 40.615,52.685 41.35,51.95 42.35,51.95 42.9,52.5 43.4,52.5 44.1,51.8 44.4,51.8 44.7,52.1 45.5,52.1 46.3,52.9 46.9,52.9 v1(47.3,53.3)
DRAM_DQM6: U1.AD24 U5.E7 | length 21.7
  L1 w0.114: v1(38.4,58.5) 38.4,57.7 U1.AD24@38.8,57.3 ; U5.E7@47.7,68.1 v1(48.1,67.7)
  L8 w0.12: v1(38.4,58.5) 38.5,58.5 38.8,58.8 38.8,61.635 38.965,61.8 39.5,61.8 39.8,62.1 39.8,63.1 39.4,63.5 39.4,64.2 39.8,64.6 40.1,64.6 40.3,64.4 40.3,64 40.5,63.8 40.9,63.8 41.1,64 41.1,65.7 43.3,67.9 43.8,67.9 44.262,67.438 45.938,67.438 46.18,67.68 46.18,67.95 46.38,68.15 46.65,68.15 47,67.8 48,67.8 v1(48.1,67.7)
DRAM_DQM7: U1.Y21 U5.D3 | length 19.1
  L1 w0.114: v1(35.2,55.3) U1.Y21@35.6,54.9 ; v1(46.5,65.3) U5.D3@46.9,64.9
  L3 w0.12: v1(35.2,55.3) 35.585,55.685 36.129,55.685 36.385,55.941 36.385,56.229 36.671,56.515 37.759,56.515 38.015,56.771 38.015,57.059 38.356,57.4 39.465,57.4 40.4,58.335 40.4,58.6 42.2,60.4 ; 42.2,60.407 43.107,60.407 43.372,60.672 44.316,60.672 45.65,62.006 45.65,62.35 45.285,62.715 45.285,64.685 45.515,64.915 46.115,64.915 v1(46.5,65.3)
DRAM_DQS0_N: U1.AD3 U2.G3 | length 19.1
  L1 w0.1: U1.AD3@38.8,40.5 39.077,40.5 39.477,40.1 40.157,40.1 40.68,39.577 40.68,38.792 41.8,37.672 v1(41.8,37.1) ; v1(48.9,28.5) U2.G3@49.3,28.9
  L8 w0.11: v1(41.8,37.1) 41.894,37.006 41.894,36.443 42.48,35.857 42.48,35.448 44.08,33.848 44.08,31.792 45.152,30.72 47.408,30.72 47.72,30.408 47.72,28.908 48.128,28.5 v1(48.9,28.5)
DRAM_DQS0_P: U1.AE3 U2.F3 | length 19.1
  L1 w0.1: U1.AE3@39.6,40.5 39.68,40.42 40.289,40.42 41,39.709 41,38.925 41.2,38.725 41.725,38.725 41.85,38.6 41.85,38.075 42.12,37.805 42.12,37.48 42.4,37.2 v1(42.4,37.1) ; U2.F3@48.5,28.9 v1(48.9,29.3)
  L8 w0.11: v1(42.4,37.1) 42.4,36.972 42.214,36.786 42.214,36.576 42.8,35.99 42.8,35.581 44.4,33.981 44.4,31.925 45.285,31.04 47.541,31.04 48.04,30.541 48.04,30.2 48.327,29.913 48.327,29.527 48.04,29.24 48.04,29.041 48.261,28.82 48.492,28.82 48.9,29.228 v1(48.9,29.3)
DRAM_DQS1_N: U1.AE6 U2.B7 | length 20.5
  L1 w0.1: U1.AE6@39.6,42.9 39.68,42.82 40.929,42.82 41.52,42.229 41.52,41.92 41.866,41.574 41.866,41.266 41.52,40.92 41.52,40.68 41.8,40.4 v1(41.8,40.3) ; U2.B7@45.3,32.1 v1(45.7,31.7)
  L3 w0.11: v1(41.8,40.3) 41.66,40.16 41.66,39.982 42.82,38.822 42.82,37.833 43.12,37.533 43.12,35.533 44.22,34.433 44.22,33.748 43.78,33.308 43.78,32.892 44.28,32.392 44.28,31.092 44.472,30.9 44.7,30.9 44.889,31.089 45.089,31.089 45.289,30.889 45.289,30.689 45.1,30.5 45.1,30.272 45.267,30.105 45.733,30.105 46.18,30.552 46.18,31.314 45.794,31.7 v1(45.7,31.7)
DRAM_DQS1_P: U1.AD6 U2.C7 | length 20.5
  L1 w0.1: U1.AD6@38.8,42.9 39.077,42.9 39.477,42.5 40.797,42.5 41.2,42.097 v1(41.2,40.3) ; U2.C7@46.107,32.093 v1@46.5,31.7
  L3 w0.11: v1(41.2,40.3) 41.34,40.16 41.34,39.849 42.5,38.689 42.5,37.7 42.8,37.4 42.8,35.4 43.9,34.3 43.9,33.881 43.46,33.441 43.46,32.759 43.96,32.259 43.96,30.959 45.134,29.785 45.866,29.785 46.5,30.419 v1(46.5,31.687)
DRAM_DQS2_N: U1.AE8 U3.G3 | length 19.1
  L1 w0.1: U1.AE8@39.6,44.5 39.68,44.42 41.18,44.42 41.45,44.15 41.65,44.15 41.85,44.35 42.075,44.35 42.35,44.075 42.35,43.85 42.15,43.65 42.15,43.45 42.4,43.2 42.941,43.2 43.3,43.559 43.3,44.5 42.8,45 42.8,45.609 43.111,45.92 43.292,45.92 43.572,46.2 v1(43.7,46.2) ; U3.G3@49.3,40.9 v1(49.7,40.5)
  L3 w0.11: v1(43.7,46.2) 43.784,46.116 44.317,46.116 45.3,45.132 45.3,44.2 46.185,43.315 46.534,43.315 46.819,43.6 48,43.6 48.5,43.1 48.5,42.6 49.7,41.4 v1(49.7,40.5)
DRAM_DQS2_P: U1.AD8 U3.F3 | length 19.1
  L1 w0.1: U1.AD8@38.8,44.5 39.077,44.5 39.477,44.1 41.047,44.1 42.267,42.88 43.073,42.88 43.62,43.427 43.62,44.633 43.12,45.133 43.12,45.477 43.243,45.6 v1(43.7,45.6) ; U3.F3@48.5,40.9 v1(48.9,40.5)
  L3 w0.11: v1(43.7,45.6) 43.793,45.6 43.989,45.796 44.184,45.796 44.98,45 44.98,44.067 46.053,42.995 46.666,42.995 46.952,43.28 47.867,43.28 48.18,42.967 48.18,42.467 48.55,42.097 48.55,41.713 48.763,41.5 49.147,41.5 49.38,41.267 49.38,40.873 49.007,40.5 v1(48.9,40.5)
DRAM_DQS3_N: U1.AB10 U3.B7 | length 15.4
  L1 w0.1: U1.AB10@37.2,46.1 v1(37.6,45.7) ; U3.B7@45.3,44.1 45.3,42.491 45.691,42.1 v1(47.2,42.1)
  L8 w0.11: v1(37.6,45.7) 37.704,45.804 38.048,45.804 39.152,44.7 42.7,44.7 45.02,42.38 46.827,42.38 47.107,42.1 v1(47.2,42.1)
DRAM_DQS3_P: U1.AC10 U3.C7 | length 15.4
  L1 w0.1: v1(37.6,46.5) U1.AC10@38,46.1 ; U3.C7@46.1,44.1 45.9,44.1 45.62,43.82 45.62,43.58 45.74,43.46 45.74,43.24 45.62,43.12 45.62,42.623 45.823,42.42 46.792,42.42 47.072,42.7 v1(47.2,42.7)
  L8 w0.11: v1(37.6,46.5) 37.976,46.124 38.18,46.124 39.284,45.02 42.833,45.02 45.153,42.7 v1(47.2,42.7)
DRAM_DQS4_N: U1.AE18 U4.G3 | length 16.4
  L1 w0.1: U1.AE18@39.6,52.5 39.68,52.58 40.195,52.58 40.405,52.37 40.695,52.37 40.905,52.58 41.78,52.58 42.3,53.1 v1(42.3,53.2) ; v1(48.9,52.5) U4.G3@49.3,52.9
  L3 w0.11: v1(42.3,53.2) 42.16,53.34 42.16,53.829 42.466,54.135 42.731,54.135 42.818,54.048 43.018,54.048 43.218,54.248 43.218,54.448 43.131,54.535 43.131,54.8 43.481,55.15 43.969,55.15 44.22,54.899 44.22,53.327 44.652,52.895 45.448,52.895 45.92,53.367 45.92,54.439 46.141,54.66 46.5,54.66 48.43,52.73 48.67,52.73 v1(48.9,52.5)
DRAM_DQS4_P: U1.AD18 U4.F3 | length 16.4
  L1 w0.1: U1.AD18@38.8,52.5 39.07,52.5 39.47,52.9 41.45,52.9 41.7,53.15 v1(41.7,53.2) ; U4.F3@48.5,52.9 v1(48.9,53.3)
  L3 w0.11: v1(41.7,53.2) 41.84,53.34 41.84,53.962 43.348,55.47 44.102,55.47 44.54,55.032 44.54,53.46 44.785,53.215 45.315,53.215 45.6,53.5 45.6,54.572 46.008,54.98 46.633,54.98 48.543,53.07 48.67,53.07 v1(48.9,53.3)
DRAM_DQS5_N: U1.AE20 U4.B7 | length 14.4
  L1 w0.1: U1.AE20@39.6,54.1 39.68,54.18 40.42,54.18 40.683,53.917 41.017,53.917 41.28,54.18 41.58,54.18 42.1,54.7 v1(42.1,54.8) ; U4.B7@45.3,56.1 45.54,55.86 45.54,55.507 45.947,55.1 47.49,55.1 47.69,54.9 47.69,54.74 v1(47.55,54.6)
  L8 w0.11: v1(42.1,54.8) 41.96,54.66 41.96,54.5 42.16,54.3 42.9,54.3 43.1,54.5 43.1,54.875 43.3,55.075 43.6,55.075 43.8,54.875 43.8,54.5 44,54.3 45.709,54.3 45.909,54.5 46.761,54.5 47.161,54.1 47.48,54.1 47.68,54.3 47.68,54.47 v1(47.55,54.6)
DRAM_DQS5_P: U1.AD20 U4.C7 | length 14.4
  L1 w0.1: U1.AD20@38.8,54.1 39,54.1 39.4,54.5 41.35,54.5 41.5,54.65 v1(41.5,54.8) ; U4.C7@46.1,56.1 45.86,55.86 45.86,55.64 46.08,55.42 47.623,55.42 48.01,55.033 48.01,54.74 v1(48.15,54.6)
  L8 w0.11: v1(41.5,54.8) 41.64,54.66 41.64,54.367 42.027,53.98 45.842,53.98 46.042,54.18 46.629,54.18 47.029,53.78 47.613,53.78 48,54.167 48,54.45 v1(48.15,54.6)
DRAM_DQS6_N: U1.AE23 U5.G3 | length 21.7
  L1 w0.1: U1.AE23@39.6,56.5 39.68,56.58 40.28,56.58 40.5,56.8 40.97,56.8 41.15,56.98 41.15,57.45 41.36,57.66 41.36,58.64 40.52,59.48 40.52,59.72 40.8,60 v1(40.8,60.1) ; v1(48.9,64.5) U5.G3@49.3,64.9
  L8 w0.11: v1(40.8,60.1) 40.8,60.193 40.52,60.473 40.52,60.667 41.52,61.667 41.52,62.167 42.033,62.68 43.733,62.68 44.32,63.267 44.32,64.033 43.833,64.52 43.273,64.52 42.91,64.883 42.91,65.317 43.373,65.78 44.02,65.78 44.225,65.575 44.475,65.575 44.68,65.78 47.267,65.78 48.067,64.98 48.52,64.98 48.9,64.6 v1(48.9,64.5)
DRAM_DQS6_P: U1.AD23 U5.F3 | length 21.7
  L1 w0.1: U1.AD23@38.8,56.5 39.077,56.5 39.477,56.9 40.147,56.9 41.04,57.793 41.04,58.507 40.2,59.347 v1(40.2,60.1) ; U5.F3@48.5,64.9 v1(48.9,65.3)
  L8 w0.11: v1(40.2,60.1) 40.2,60.8 41.2,61.8 41.2,62.3 41.9,63 43.6,63 44,63.4 44,63.9 43.7,64.2 43.14,64.2 42.59,64.75 42.59,65.45 43.24,66.1 47.4,66.1 48.2,65.3 v1(48.9,65.3)
DRAM_DQS7_N: U1.AA24 U5.B7 | length 19.2
  L1 w0.1: U1.AA24@36.4,57.3 36.4,57.5 36.8,57.9 36.8,58.847 36.92,58.967 36.92,59.352 39.708,62.14 40.017,62.14 40.4,61.757 v1(40.4,61.7) ; U5.B7@45.3,68.1 45.3,67.3 46.1,66.5 v1(46.8,66.5)
  L3 w0.11: v1(40.4,61.7) 40.48,61.62 41.192,61.62 41.88,62.308 41.88,62.697 43.19,64.007 43.19,65.249 43.813,65.872 45.392,65.872 46.065,66.545 46.755,66.545 v1(46.8,66.5)
DRAM_DQS7_P: U1.AA25 U5.C7 | length 19.2
  L1 w0.1: U1.AA25@36.4,58.1 36.48,58.18 36.48,58.98 36.6,59.1 36.6,59.485 38.9,61.785 38.9,62.15 39.035,62.285 39.4,62.285 39.575,62.46 40.149,62.46 40.394,62.215 40.685,62.215 v1(40.7,62.2) ; U5.C7@46.1,68.1 45.895,68.1 45.62,67.825 45.62,67.433 46.233,66.82 46.42,66.82 46.7,67.1 v1(46.9,67.1)
  L3 w0.11: v1(40.7,62.2) 40.7,62.128 40.888,61.94 41.059,61.94 41.56,62.441 41.56,62.83 42.87,64.14 42.87,65.381 43.68,66.192 45.259,66.192 45.933,66.865 46.425,66.865 46.66,67.1 v1(46.9,67.1)
DRAM_RAS_B: R34.1 U1.AB15 U2.J3 U3.J3 U4.J3 U5.J3 | length 109.6
  L1 w0.114: U1.AB15@37.2,50.1 v1(37.6,50.5) ; U2.J3@50.9,28.9 v1(50.9,29.5) ; U3.J3@50.9,40.9 v1(50.9,41.5) ; U4.J3@50.9,52.9 v1(50.9,53.5) ; U5.J3@50.9,64.9 v1(50.9,65.5) ; v1(52.1,23.2) 52.5,23.6 R34.1@52.635,23.6
  L3 w0.12: v1(47.8,71.6) 47.3,71.1 47.3,70.7 47.5,70.5 49.1,70.5 49.3,70.3 49.3,69.9 49.1,69.7 47.9,69.7 47.7,69.5 47.7,69.1 47.9,68.9 49.9,68.9 50.1,68.7 50.1,68.3 49.9,68.1 48.7,68.1 48.5,67.9 48.5,65.9 48.7,65.7 49.1,65.7 49.3,65.9 49.3,66.5 49.5,66.7 50.7,66.7 50.9,66.5 v1(50.9,65.5) 50.9,65.1 50.58,64.78 50.58,64.38 50.2,64 50.2,63.6 50.58,63.22 50.58,62.78 50,62.2 50,59.3 50.3,59 50.3,56.3 50,56 50,55.434 50.9,54.534 v1(50.9,53.5) 50.9,53.1 50.58,52.78 50.58,52.38 50.2,52 50.2,51.6 50.58,51.22 50.58,50.78 50,50.2 50,47.3 50.3,47 50.3,44.3 50,44 50,43.434 50.9,42.534 v1(50.9,41.5) 50.9,41.1 50.58,40.78 50.58,40.38 50.2,40 50.2,39.6 50.58,39.22 50.58,38.78 50,38.2 50,35.3 50.3,35 50.3,32.3 50,32 50,31.434 50.9,30.534 v1(50.9,29.5) 50.3,28.9 50.3,28.48 50.58,28.2 50.58,26.98 50.38,26.78 50.18,26.78 49.9,26.5 49.9,26 50.115,25.785 50.659,25.785 50.9,25.544 50.9,25 50.7,24.8 50.1,24.8 49.8,24.5 49.8,24.1 50.1,23.8 51.5,23.8 v1(52.1,23.2)
  L10 w0.114: v1(37.6,50.5) 37.815,50.5 38.215,50.9 39.356,50.9 41.256,52.8 41.66,52.8 42.16,52.3 42.5,52.3 43.3,53.1 43.3,54.4 42.9,54.8 42.9,55.1 43.18,55.38 43.48,55.38 43.7,55.6 43.7,56.015 43.465,56.25 43.465,56.435 43.3,56.6 43.3,56.9 43.8,57.4 43.8,58.3 44,58.5 44.25,58.5 44.417,58.668 44.417,59.033 44.235,59.215 43.085,59.215 42.9,59.4 42.9,59.8 43.1,60 44.4,60 44.6,60.2 44.9,60.2 45.1,60.4 45.1,60.8 44.9,61 44.3,61 44.1,61.2 44.1,61.6 44.3,61.8 44.8,61.8 45.1,62.1 45.95,62.1 46.15,62.3 46.15,62.65 45.285,63.515 45.285,64.659 45.059,64.885 44.615,64.885 44.2,65.3 44.2,65.7 44.564,66.064 44.564,67.564 45.3,68.3 45.3,68.644 45.556,68.9 46.7,68.9 46.9,69.1 46.9,69.5 46.7,69.7 46.3,69.7 46.1,69.9 46.1,70.3 46.3,70.5 48.3,70.5 48.5,70.7 48.5,71.156 48.056,71.6 v1(47.8,71.6)
DRAM_RESET_B: R7.2 U1.Y6 U2.T2 U3.T2 U4.T2 U5.T2 | length 101.3
  L1 w0.114: v1(35.2,43.3) U1.Y6@35.6,42.9 ; U2.T2@56.5,28.1 57.1,28.1 57.4,28.4 57.4,28.8 v1(58.1,29.5) ; U3.T2@56.5,40.1 v1(58.1,40.1) ; U4.T2@56.5,52.1 v1(58.1,52.1) ; U5.T2@56.5,64.1 57.1,64.1 57.9,64.9 v1(58.1,64.9)
  L8 w0.12: v1(57.7,71.8) 57.75,71.75 57.75,69.22 58.1,68.87 v1(58.1,64.9) 58.1,59.4 58.9,58.6 58.9,55.9 57.9,54.9 57.9,53.6 58.1,53.4 v1(58.1,52.1) 58.1,51.1 59.135,50.065 59.135,44.135 57.6,42.6 57.6,41.855 58.1,41.355 v1(58.1,40.1) 58.1,39.6 58.3,39.4 58.3,35.444 59.085,34.659 59.085,33.341 58.5,32.756 58.5,31.4 58.1,31 v1(58.1,29.5)
  L10 w0.114: v1(35.2,43.3) 35.456,43.3 35.871,42.885 42.085,42.885 42.515,43.315 47.915,43.315 48.7,44.1 51.956,44.1 53.641,45.785 54.085,45.785 55.015,46.715 55.015,47.759 55.1,47.844 55.1,49.7 55.285,49.885 55.285,50.985 55.685,51.385 55.685,57.085 56.2,57.6 56.2,60.9 56.5,61.2 56.5,65.2 56.815,65.515 56.815,68.659 57.7,69.544 v1(57.7,71.8)
DRAM_SDBA0: R2.1 U1.AC15 U2.M2 U3.M2 U4.M2 U5.M2 | length 109.4
  L1 w0.114: U1.AC15@38,50.1 v1(38.4,50.5) ; v1(52.9,28.5) U2.M2@53.3,28.1 ; v1(52.9,40.5) U3.M2@53.3,40.1 ; v1(52.9,52.5) U4.M2@53.3,52.1 ; v1(52.9,64.5) U5.M2@53.3,64.1 ; R2.1@57.9,23.035 57.9,22.5 v1(58.2,22.2)
  L3 w0.12: v1(50.2,72.6) 50.5,72.6 52.1,71 52.1,66.066 52.5,65.666 52.5,65.3 52.9,64.9 v1(52.9,64.5) 52.778,64.378 52.56,64.378 52.1,63.918 52.1,61.2 51.475,60.575 51.475,60.19 51.9,59.765 51.9,59.3 52.1,59.1 52.1,54.066 52.566,53.6 52.566,53.234 52.9,52.9 v1(52.9,52.5) 52.778,52.378 52.56,52.378 52.1,51.918 52.1,49.2 51.475,48.575 51.475,48.19 51.9,47.765 51.9,47.3 52.1,47.1 52.1,42.066 52.566,41.6 52.566,41.234 52.9,40.9 v1(52.9,40.5) 52.778,40.378 52.56,40.378 52.1,39.918 52.1,37.2 51.475,36.575 51.475,36.19 51.9,35.765 51.9,35.3 52.1,35.1 52.1,30.066 52.566,29.6 52.566,29.134 52.9,28.8 v1(52.9,28.5) 52.5,28.1 52.5,26.4 53,25.9 53,25.256 54.356,23.9 56.5,23.9 v1(58.2,22.2)
  L10 w0.114: v1(38.4,50.5) 39.4,50.5 39.815,50.915 40.041,50.915 40.556,50.4 40.9,50.4 41.115,50.615 41.115,51.515 41.31,51.71 42.77,51.71 43.16,52.1 45.1,52.1 45.5,52.5 45.5,54.1 45.3,54.3 44.9,54.3 44.7,54.1 44.7,53 44.5,52.8 44.1,52.8 43.9,53 43.9,54.8 44.1,55 45.3,55 45.5,55.2 45.5,55.7 46.1,56.3 46.1,56.7 45.885,56.915 44.585,56.915 44.38,57.12 44.38,57.48 44.615,57.715 45.815,57.715 46.1,58 46.1,58.3 46.3,58.5 46.7,58.5 47,58.8 47,59.1 46.8,59.3 46.8,60 47.2,60.4 47.2,60.7 46.8,61.1 46.8,62 47.3,62.5 47.3,63.1 46.9,63.5 46.9,63.844 47.3,64.244 47.3,64.64 47.6,64.94 47.6,65.3 47.215,65.685 45.515,65.685 ; 45.5,65.7 45.285,65.915 45.285,66.215 45.485,66.415 46.185,66.415 46.4,66.63 46.4,66.93 46.2,67.13 45.7,67.13 45.485,67.345 45.485,67.645 45.66,67.82 46.5,67.82 46.82,67.5 47.2,67.5 47.4,67.7 47.4,68.056 48.515,69.171 48.515,69.459 48.741,69.685 49.029,69.685 49.785,70.441 49.785,71.905 50.2,72.32 v1(50.2,72.6)
DRAM_SDBA1: R11.1 U1.Y15 U2.N8 U3.N8 U4.N8 U5.N8 | length 109.5
  L1 w0.114: U1.Y15@35.6,50.1 v1(36,50.5) ; v1(53.7,32.5) U2.N8@54.1,32.9 ; v1(53.7,44.5) U3.N8@54.1,44.9 ; v1(53.7,56.5) U4.N8@54.1,56.9 ; v1(53.7,68.5) U5.N8@54.1,68.9 ; R11.1@56,24.165 56,24.365 56.4,24.765 56.4,25.5 v1(56,25.9)
  L3 w0.12: v1(49.8,75) 49.5,74.7 49.5,74.4 49.7,74.2 50.6,74.2 51,74.6 51.344,74.6 51.885,74.059 51.885,73.685 51.5,73.3 51.5,72.556 51.841,72.215 52.159,72.215 52.4,72.456 52.4,73.1 52.6,73.3 53,73.3 53.2,73.1 53.2,72.456 53.8,71.856 53.8,71 53.6,70.8 53.6,69.8 53.315,69.515 53.315,69.141 53.7,68.756 v1(53.7,68.5) 53.7,65.334 54.1,64.934 54.1,63.5 53.7,63.1 53.7,61.844 53.985,61.559 53.985,61.1 53.625,60.74 53.625,60.275 53.885,60.015 53.885,59.385 53.45,58.95 53.45,58.6 53.7,58.35 53.7,57.844 53.315,57.459 53.315,56.885 v1(53.7,56.5) 53.7,53.334 54.1,52.934 54.1,51.5 53.7,51.1 53.7,49.844 53.985,49.559 53.985,49.1 53.625,48.74 53.625,48.275 53.885,48.015 53.885,47.385 53.45,46.95 53.45,46.6 53.7,46.35 53.7,45.844 53.315,45.459 53.315,44.885 v1(53.7,44.5) 53.7,41.334 54.1,40.934 54.1,39.5 53.7,39.1 53.7,37.844 53.985,37.559 53.985,37.1 53.625,36.74 53.625,36.275 53.885,36.015 53.885,35.385 53.45,34.95 53.45,34.6 53.7,34.35 53.7,33.844 53.315,33.459 53.315,32.885 v1(53.7,32.5) 53.7,31.356 53.544,31.2 53.544,30.856 54.1,30.3 54.1,30.1 53.7,29.7 53.7,29.334 54.2,28.834 54.2,28.3 53.965,28.065 53.965,27.606 54.5,27.071 54.5,26.2 54.9,25.8 55.4,25.8 55.5,25.9 v1(56,25.9)
  L10 w0.114: v1(36,50.5) 36,51.556 36.415,51.971 36.415,53.059 36.641,53.285 36.929,53.285 37.185,53.541 37.185,53.885 37.415,54.115 37.759,54.115 38,54.356 38,55.9 39.2,57.1 39.2,57.9 38.785,58.315 38.785,58.629 39.3,59.144 39.3,59.5 39,59.8 38.1,59.8 37.567,60.333 37.567,61.567 38.433,62.433 38.433,63.933 38.7,64.2 38.7,65.6 39.3,66.2 39.3,67.1 39,67.4 39,68.044 39.2,68.244 39.2,69.956 39.885,70.641 39.885,71.385 40.2,71.7 41.044,71.7 41.285,71.941 41.285,72.685 42.8,74.2 42.8,75.5 43,75.7 43.4,75.7 43.6,75.5 43.6,74.7 43.8,74.5 44.2,74.5 44.4,74.7 44.4,75.5 44.6,75.7 45,75.7 45.2,75.5 45.2,74.7 45.4,74.5 45.8,74.5 46,74.7 46,75.5 46.2,75.7 46.6,75.7 47.3,75 v1(49.8,75)
DRAM_SDBA2: R22.1 U1.AB12 U2.M3 U3.M3 U4.M3 U5.M3 | length 109.6
  L1 w0.114: U1.AB12@37.2,47.7 v1(37.6,47.3) ; U2.M3@53.3,28.9 v1(53.3,29.5) ; U3.M3@53.3,40.9 v1(53.3,41.5) ; U4.M3@53.3,52.9 v1(53.3,53.5) ; U5.M3@53.3,64.9 v1(53.3,65.5) ; v1(59.2,24.2) 59.465,24.465 R22.1@59.7,24.465
  L3 w0.12: v1(52.8,72.6) 52.8,72.46 53,72.26 53,71.434 53.285,71.149 53.285,69.885 52.9,69.5 52.9,69.16 53.315,68.745 53.315,68.315 52.9,67.9 52.9,67.3 53.3,66.9 53.3,66.7 53,66.4 53,66.1 53.3,65.8 v1(53.3,65.5) 53.3,65.296 53.6,64.996 53.6,63.7 52.9,63 52.9,62.2 53.2,61.9 53.2,61.2 53.1,61.1 53.1,58.5 53.38,58.22 53.38,57.92 52.9,57.44 52.9,56.9 53.2,56.6 53.2,55.944 52.9,55.644 52.9,54.8 53.3,54.4 v1(53.3,53.5) 53.3,53.296 53.6,52.996 53.6,51.7 52.9,51 52.9,50.2 53.2,49.9 53.2,49.2 53.1,49.1 53.1,46.5 53.38,46.22 53.38,45.92 52.9,45.44 52.9,44.9 53.2,44.6 53.2,43.944 52.9,43.644 52.9,42.8 53.3,42.4 v1(53.3,41.5) 53.3,41.296 53.6,40.996 53.6,39.7 52.9,39 52.9,38.2 53.2,37.9 53.2,37.2 53.1,37.1 53.1,34.5 53.38,34.22 53.38,33.92 52.9,33.44 52.9,32.9 53.2,32.6 53.2,31.944 52.9,31.644 52.9,30.8 53.3,30.4 v1(53.3,29.5) 53.3,29.282 53.62,28.962 53.62,27.498 53.7,27.418 53.7,26.444 54.585,25.559 54.585,25.271 54.841,25.015 55.315,25.015 55.7,25.4 56.166,25.4 57.766,23.8 58.8,23.8 v1(59.2,24.2)
  L10 w0.114: v1(37.6,47.3) 38,47.7 38,48.3 38.2,48.5 38.6,48.5 38.8,48.3 38.8,47.9 39,47.7 39.4,47.7 39.6,47.9 39.6,48.3 39.785,48.485 42.115,48.485 42.6,48 45.7,48 46.1,48.4 46.715,48.4 46.915,48.6 50,48.6 50.22,48.82 50.22,49.266 50.066,49.42 49.78,49.42 49.09,50.11 49.09,50.5 49.3,50.71 49.3,51.1 49.1,51.3 48.71,51.3 48.5,51.51 48.5,51.9 48.7,52.1 49.1,52.1 49.3,52.3 49.3,52.7 49.485,52.885 49.9,52.885 50.2,53.185 50.2,54 50.4,54.2 50.7,54.2 50.956,54.456 50.956,54.83 50.713,55.073 50.383,55.073 50.015,55.441 50.015,55.815 50.215,56.015 50.6,56.015 50.8,56.215 50.8,56.615 50.6,56.815 50.325,56.815 50.115,57.025 50.115,57.415 50.315,57.615 50.615,57.615 50.815,57.815 50.815,58.215 50.615,58.415 50.465,58.415 50.265,58.615 50.265,59.015 50.465,59.215 51.159,59.215 51.385,59.441 51.385,60.326 50.515,61.196 50.515,61.615 50.9,62 50.9,64.7 51.3,65.1 51.3,65.8 52,66.5 52,67 51.7,67.3 51.7,67.9 52.254,68.454 52.254,68.954 52.515,69.215 52.515,70.315 52.7,70.5 53.1,70.5 53.4,70.8 53.4,71.056 53,71.456 53,71.9 52.8,72.1 v1(52.8,72.6)
DRAM_SDCKE0: R6.2 R45.1 U1.Y11 U2.K9 U3.K9 U4.K9 U5.K9 | length 109.5
  L1 w0.114: v1(35.2,47.3) U1.Y11@35.6,46.9 ; v1(51.3,25.4) 51.5,25.2 R45.1@51.5,24.865 ; v1(51.3,34.1) U2.K9@51.7,33.7 ; v1(51.3,46.1) U3.K9@51.7,45.7 ; v1(51.3,58.1) U4.K9@51.7,57.7 ; v1(51.3,70.1) U5.K9@51.7,69.7
  L3 w0.12: v1(45.4,70.8) 45.8,70.8 46.1,70.5 46.1,69.3 46.3,69.1 46.7,69.1 46.885,69.285 46.885,70.723 46.615,70.993 46.615,71.8 46.815,72 47.215,72 47.415,72.2 47.415,72.885 47.615,73.085 48.015,73.085 48.215,72.885 48.215,71.085 48.435,70.865 49.235,70.865 49.6,70.5 49.6,69.885 49.785,69.7 50.1,69.7 50.8,70.4 51.1,70.4 51.3,70.2 v1(51.3,70.1) 51.3,69.844 50.9,69.444 50.9,68.8 50.625,68.525 50.625,67.919 50.8,67.744 50.8,67.1 51.3,66.6 51.3,65.066 50.9,64.666 50.9,62.5 50.4,62 50.4,59.515 51.3,58.615 v1(51.3,58.1) 51.3,57.844 50.9,57.444 50.9,56.8 50.625,56.525 50.625,55.919 50.8,55.744 50.8,55.1 51.3,54.6 51.3,53.066 50.9,52.666 50.9,50.5 50.4,50 50.4,47.515 51.3,46.615 v1(51.3,46.1) 51.3,45.844 50.9,45.444 50.9,44.8 50.625,44.525 50.625,43.919 50.8,43.744 50.8,43.1 51.3,42.6 51.3,41.066 50.9,40.666 50.9,38.5 50.4,38 50.4,35.515 51.3,34.615 v1(51.3,34.1) 50.8,33.6 50.8,31.1 51.3,30.6 51.3,29.044 51.7,28.644 51.7,28.356 51.459,28.115 51.17,28.115 50.9,27.844 50.9,26.9 51.725,26.075 51.725,25.6 51.525,25.4 v1(51.3,25.4)
  L10 w0.114: v1(35.2,47.3) 35.465,47.565 R6.2@35.8,47.565 36.065,47.565 36.405,47.905 36.405,49.905 36.615,50.115 36.959,50.115 37.185,50.341 37.185,50.629 37.471,50.915 37.759,50.915 38.015,51.171 38.015,51.56 38.17,51.715 38.58,51.715 38.965,52.1 39.5,52.1 41.1,53.7 41.1,55.41 42,56.31 42,57.4 42.2,57.6 42.9,57.6 43.1,57.8 43.1,58.2 42.915,58.385 42.315,58.385 42.1,58.6 42.1,59.9 42.4,60.2 42.4,60.7 42,61.1 42,62 42.28,62.28 42.88,62.28 43.085,62.485 43.085,62.815 42.885,63.015 42.185,63.015 42,63.2 42,63.6 42.2,63.8 42.704,63.8 43,64.096 43,64.4 42.8,64.6 42,64.6 41.5,65.1 41.5,65.4 42.1,66 43.7,66 43.885,66.185 43.885,66.515 43.685,66.715 42.685,66.715 42.5,66.9 42.5,67.3 42.7,67.5 43.7,67.5 43.885,67.685 43.885,67.97 43.415,68.441 43.415,68.815 43.7,69.1 43.7,70.7 43.9,70.9 44.3,70.9 44.5,70.7 44.5,69.9 44.7,69.7 45.2,69.7 45.4,69.9 v1(45.4,70.8)
DRAM_SDODT0: R77.1 U1.AC16 U2.K1 U3.K1 U4.K1 U5.K1 | length 109.5
  L1 w0.114: U1.AC16@38,50.9 v1(38.4,51.3) ; R77.1@51.6,23.035 51.6,22.5 v1(51.9,22.2) ; U2.K1@51.7,27.3 v1(52.1,27.7) ; v1(51.7,38.7) U3.K1@51.7,39.3 ; v1(51.7,50.7) U4.K1@51.7,51.3 ; v1(51.7,62.7) U5.K1@51.7,63.3
  L8 w0.12: v1(49.4,72.6) 49.8,73 50.5,73 51,72.5 51,72.1 51.4,71.7 51.4,70.8 51.7,70.5 51.7,67.234 51.9,67.034 51.9,66.1 51.7,65.9 v1(51.7,62.7) 51.7,61.966 51.3,61.566 51.3,60.3 51.525,60.075 51.525,59.581 51.2,59.256 51.2,58.744 51.7,58.244 51.7,54 51.3,53.6 51.3,53.2 51.7,52.8 51.7,52.356 52.15,51.906 52.15,51.65 51.7,51.2 v1(51.7,50.7) 51.7,49.966 51.3,49.566 51.3,48.3 51.525,48.075 51.525,47.581 51.2,47.256 51.2,46.744 51.7,46.244 51.7,42 51.3,41.6 51.3,41.2 51.7,40.8 51.7,40.356 52.15,39.906 52.15,39.65 51.7,39.2 v1(51.7,38.7) 51.7,37.966 51.3,37.566 51.3,36.2 51.7,35.8 51.7,35.4 51.5,35.2 51.1,35.2 50.915,35.015 50.915,33.885 51.1,33.7 51.5,33.7 51.7,33.5 51.7,31.1 51.98,30.82 51.98,30.28 51.8,30.1 51.5,30.1 51.285,29.885 51.285,29.215 51.7,28.8 51.7,28.356 52.1,27.956 v1(52.1,27.7) 52.1,27 51.926,26.826 51.626,26.826 51.4,26.6 51.4,26.3 51.6,26.1 51.8,26.1 52.05,25.85 52.05,25.55 51.45,24.95 51.45,24.65 51.7,24.4 52.7,24.4 52.9,24.2 52.9,23.8 52.7,23.6 51.235,23.6 51.035,23.4 51.035,23 51.235,22.8 51.7,22.8 51.9,22.6 v1(51.9,22.2)
  L10 w0.114: v1(38.4,51.3) 38.656,51.3 39.056,51.7 39.6,51.7 41.5,53.6 41.5,53.9 41.7,54.1 42,54.1 42.5,53.6 42.8,53.6 43,53.8 43,54.304 42.504,54.8 42.504,55.395 42.779,55.67 42.97,55.67 43.185,55.885 43.185,56.285 42.985,56.485 42.485,56.485 42.3,56.67 42.3,57.07 42.5,57.27 43.17,57.27 43.4,57.5 43.4,58.7 43.2,58.9 42.8,58.9 42.5,59.2 42.5,59.9 42.9,60.3 43.9,60.3 44.1,60.5 44.1,60.8 43.9,61 ; 43.885,61.015 42.485,61.015 42.3,61.2 42.3,61.8 42.5,62 43.056,62 43.656,62.6 43.967,62.6 44.067,62.5 45.144,62.5 45.344,62.7 45.344,63.06 45.104,63.3 43.4,63.3 43.2,63.5 43.2,63.9 43.4,64.1 44.2,64.1 44.4,64.3 44.4,64.7 44.2,64.9 42.5,64.9 42.3,65.1 42.3,65.5 42.5,65.7 43.8,65.7 44.196,66.096 44.196,68.641 44.455,68.9 45.16,68.9 45.8,69.54 45.8,70.6 46.107,70.908 47.207,70.908 47.4,71.1 47.4,71.9 47.7,72.2 49,72.2 v1(49.4,72.6)
DRAM_WE_B: R42.1 U1.AB16 U2.L3 U3.L3 U4.L3 U5.L3 | length 109.5
  L1 w0.114: U1.AB16@37.2,50.9 v1(37.6,51.3) ; v1(52.1,29.3) U2.L3@52.5,28.9 ; v1(52.1,41.3) U3.L3@52.5,40.9 ; v1(52.1,53.3) U4.L3@52.5,52.9 ; v1(52.1,65.3) U5.L3@52.5,64.9 ; R42.1@52.635,22.9 52.635,22.365 v1(52.8,22.2)
  L8 w0.12: v1(49,74) 49,74.4 49.2,74.6 50,74.6 50.2,74.4 50.2,73.944 51.31,72.834 51.31,72.29 51.8,71.8 51.8,70.9 52.1,70.6 52.1,67.334 52.5,66.934 52.5,66.1 52.1,65.7 v1(52.1,65.3) 52.5,64.9 52.5,63.5 52.1,63.1 52.1,61.2 51.6,60.7 51.6,60.4 52,60 52,59.6 51.575,59.175 51.575,58.775 52.1,58.25 52.1,55.2 52.36,54.94 52.36,54.36 52.1,54.1 v1(52.1,53.3) 52.5,52.9 52.5,51.5 52.1,51.1 52.1,49.2 51.6,48.7 51.6,48.4 52,48 52,47.6 51.575,47.175 51.575,46.775 52.1,46.25 52.1,43.2 52.36,42.94 52.36,42.36 52.1,42.1 v1(52.1,41.3) 52.5,40.9 52.5,39.5 52.1,39.1 52.1,37.2 51.6,36.7 51.6,36.4 52,36 52,35.2 51.575,34.775 51.575,34.425 52.1,33.9 52.1,31.2 52.36,30.94 52.36,29.96 52.1,29.7 v1(52.1,29.3) 52.1,29.1 52.5,28.7 52.5,26.044 53,25.544 53,25.226 53.226,25 53.6,25 53.8,24.8 53.8,24.4 53.6,24.2 53.45,24.2 53.25,24 53.25,23.6 53.45,23.4 54.1,23.4 54.3,23.2 54.3,22.8 54.1,22.6 53.2,22.6 v1(52.8,22.2)
  L10 w0.114: v1(37.6,51.3) 37.725,51.425 37.725,51.681 38,51.956 38,52.244 38.271,52.515 38.559,52.515 38.785,52.741 38.941,52.741 39.7,53.5 39.7,54.2 40.4,54.9 40.4,55.5 40,55.9 40,56.3 40.2,56.5 41.1,56.5 41.3,56.7 41.3,57.1 41.1,57.3 40.55,57.3 40.35,57.5 40.35,57.9 40.55,58.1 41.3,58.1 41.5,58.3 41.5,60.7 41.185,61.015 41.185,62.415 40.6,63 40.6,64.4 40.1,64.9 40.1,65.3 41.2,66.4 41.6,66.4 41.9,66.7 41.9,67.6 42.35,68.05 42.35,68.36 42.21,68.5 41.8,68.5 41.6,68.7 41.6,69.1 41.8,69.3 42.8,69.3 43,69.5 43,69.9 42.8,70.1 41.6,70.1 41.4,70.3 41.4,70.7 41.6,70.9 42.8,70.9 43,71.1 43,71.5 42.8,71.7 42.5,71.7 42.3,71.9 42.3,72.3 42.5,72.5 42.9,72.5 43.1,72.7 43.1,73.1 43.3,73.3 43.7,73.3 43.9,73.1 43.9,72.6 44.1,72.4 44.5,72.4 44.7,72.6 44.7,73.3 44.9,73.5 45.3,73.5 45.5,73.3 ; 45.5,73.309 45.5,72.55 45.67,72.38 46.13,72.38 46.3,72.55 46.3,73 46.6,73.3 47.8,73.3 48.2,72.9 48.744,72.9 49.2,73.356 49.2,73.8 v1(49,74)
EEPROM_WP: R114.1 R115.1 U18.7 | length 3.8
  L1 w0.114: v1(61.2,36.2) 61.6,36.6 R114.1@61.6,37.6 R115.1@61.6,39
  L10 w0.114: U18.7@61.175,35.4 61.175,36.175 v1(61.2,36.2)
EN_1V375: R340.1 R341.1 U30.5 | length 17.5
  L8 w0.12: v1(12.3,31.9) 12.7,31.5 14.4,31.5 14.865,31.035 14.865,30.735 15.085,30.515 15.885,30.515 v1(16,30.4)
  L10 w0.114: v1(12.3,31.9) 12.3,32.1 12.45,32.25 U30.5@12.79,32.25 U30.5@12.9,32.25 ; v1(16,30.4) 16.1,30.3 19.7,30.3 20.2,29.8 R341.1@20.8,29.8 21.492,30.492 21.992,30.492 22.685,31.185 23.159,31.185 23.544,30.8 24.2,30.8 24.485,30.515 25.415,30.515 26.1,31.2 R340.1@26.8,31.2
EN_3V3_HDR: R403.2 R404.1 U36.5 | length 6.9
  L10 w0.114: R404.1@8.3,85.8 8.3,86 8.702,86.402 10.202,86.402 R403.2@10.5,86.7 10.5,87.1 10.7,87.3 11.756,87.3 12.1,87.644 12.1,88.6 12.5,89 U36.5@12.5,89.45
ENET_LED_LINK: J6.13 R81.2 | length 20.9
  L3 w0.12: J6.13@8.682,90.007 8.975,90.3 13.4,90.3 14,89.7 14,89.3 14.785,88.515 14.785,84.885 v1(14.4,84.5)
  L10 w0.114: R81.2@8,79.5 8,79.6 9.567,81.167 12.763,81.167 14.1,82.504 14.1,84.2 v1(14.4,84.5)
ENET_LED_RX: R82.2 R287.2 R288.2 | length 5.3
  L10 w0.114: R287.2@25.456,88.5 25.6,88.5 26.4,89.3 R82.2@26.4,89.8 26.4,92.1 R288.2@25.5,93
ENET_LED_RX_G: J6.17 R288.1 | length 2.4
  L10 w0.114: J6.17@23.718,92.547 25.171,94 R288.1@25.5,94
ENET_LED_RX_O: J6.15 R287.1 | length 1.8
  L10 w0.114: J6.15@23.718,87.467 25.467,87.467 R287.1@25.5,87.5
ENET_REF_CLK: R181.2 U1.V22 | length 26.7
  L1 w0.114: R181.2@22.1,65.4 22.6,65.4 23.15,64.85 24.65,64.85 25,64.5 25,63.6 25.2,63.4 25.6,63.4 25.8,63.6 25.8,64.5 26,64.7 26.4,64.7 26.6,64.5 26.6,63.6 26.8,63.4 27.2,63.4 27.4,63.6 27.4,64.2 27.59,64.39 ; 27.585,64.395 27.59,64.4 v1(29.1,64.4) ; U1.V22@34,55.7 v1(34.4,56.1)
  L10 w0.114: v1(29.1,64.4) 28.7,64 28.7,63.456 29.256,62.9 32.8,62.9 33.1,62.6 34.3,62.6 35.3,61.6 35.3,60 35.585,59.715 35.585,57.425 35.46,57.3 35.015,57.3 34.815,57.1 34.815,56.515 v1(34.4,56.1)
ENET_REF_CLK_R: R30.2 R181.1 U7.41 | length 3.1
  L1 w0.114: U7.41@19.04,66.35 19.5,66.35 19.65,66.5 20,66.5 20.1,66.4 R30.2@20.7,66.4 ; R30.2@20.75,66.45 20.8,66.4 R181.1@22.1,66.4
ETH_ISET: R84.1 U7.48 | length 1.7
  L1 w0.25: U7.48@19.04,69.85 19.25,69.85 v1(19.7,70.3)
  L10 w0.4: R84.1@18.9,70.5 19.5,70.5 v1(19.7,70.3)
ETH_OSCI_25MHZ: C175.1 U7.46 Y3.3 | length 4.9
  L1 w0.114: U7.46@19.04,68.85 19.85,68.85 20.1,69.1 20.1,70.1 20.6,70.6 21.45,70.6 Y3.3@22.25,71.4
ETH_OSCO_25MHZ: C176.1 U7.45 Y3.1 | length 6.3
  L1 w0.114: U7.45@19.04,68.35 19.75,68.35 C176.1@20.8,69.4 20.8,69.6 21.5,70.3 22.85,70.3 Y3.1@23.95,69.2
